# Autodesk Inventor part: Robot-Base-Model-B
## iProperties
Shininess: 21.0
Length Units: 11269
Angle Units: 11279
Time Units: 11290
Mass Units: 11283
Length Display Precision: 3
Angle Display Precision: 2
Created: 2001-08
Part Number: Robot-Base-Model-B
Document SubType Name: ﾓﾃﾞﾘﾝｸﾞ
Designer: Administrator
Density: 1 g/cm^3
Density: 0.0
Volumn: 0.0
Area: 0.0
PropertySet Name: Model Information
Control State: 0
Master: False
Checked Out: False
Author: Administrator
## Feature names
1. Extrusion1
2. Extrusion2
3. Extrusion3
4. FaceDraft
5. Chamfer1 [Fillet]
6. Chamfer2 [Fillet]
7. Chamfer3 [Fillet]
8. Hole1
9. Chamfer4 [Fillet]
10. Extrusion4
11. Shell1
